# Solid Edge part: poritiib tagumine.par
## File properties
Title: poritiib tagumine
Author: Stella-Marii
Template: Iso Metric Part.par
Last saved by: Stella-Marii
Revision: 5
Application: Solid Edge
Density: 1024,000 kg/m^3
Accuracy: 0,990
Username: Stella-Marii
Document Number: 33
Material: ABS Plastic, high impact
Face Style: Red
Fill Style: ANSI34(Plastic)
Virtual Style: Red (Shiny)
Grouping: Non-metals\Plastics
LibraryName: Materials
Coef. of Thermal Exp: 9e-05
Thermal Conductivity: 0.2
Specific Heat: 0.0
Modulus of Elasticity: 1378951400.0
Poisson's Ratio: 0.4
Yield Stress: 31026406.5
Ultimate Stress: 0.0
Elongation: 0.0
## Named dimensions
RefPlane_5: Distance = 65.4449 mm
BlueSurf_4: StartTangentMagnitude1 = 1; StartTangentMagnitude2 = 1; StartTangentMagnitude3 = 1; EndTangentMagnitude1 = 1; EndTangentMagnitude2 = 1; EndTangentMagnitude3 = 1
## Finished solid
Body 1: sheet body, 1 face, 4 edges, 4 vertices.
  Faces by surface: spline 1
  Edges by curve: spline 2, circle 1, line 1
Bounding box of the edges (mm; curved faces can reach further): 230.000 x 80.915 x 95.050, from (0, -40.6698, -65.4449) to (230, 40.2453, 29.6048).
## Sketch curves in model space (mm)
arc centre (187.5, 0, -65.4449) radius 42.5 from (201.8614, 40, -65.4449) through (229.981, -1.2708, -65.4449) to (201.8614, -40, -65.4449)
arc centre (115, 0, 12.5) radius 42.5 from (115, -40, 26.8614) through (115, 1.2708, 54.981) to (115, 40, 26.8614)
line (0, 38.0668, 0) -> (0, -34.7215, 0)
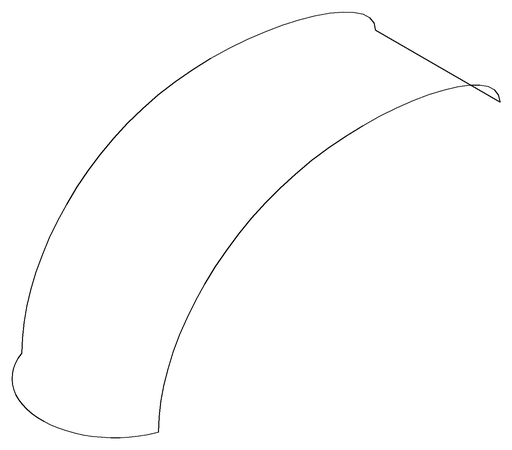
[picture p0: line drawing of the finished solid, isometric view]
